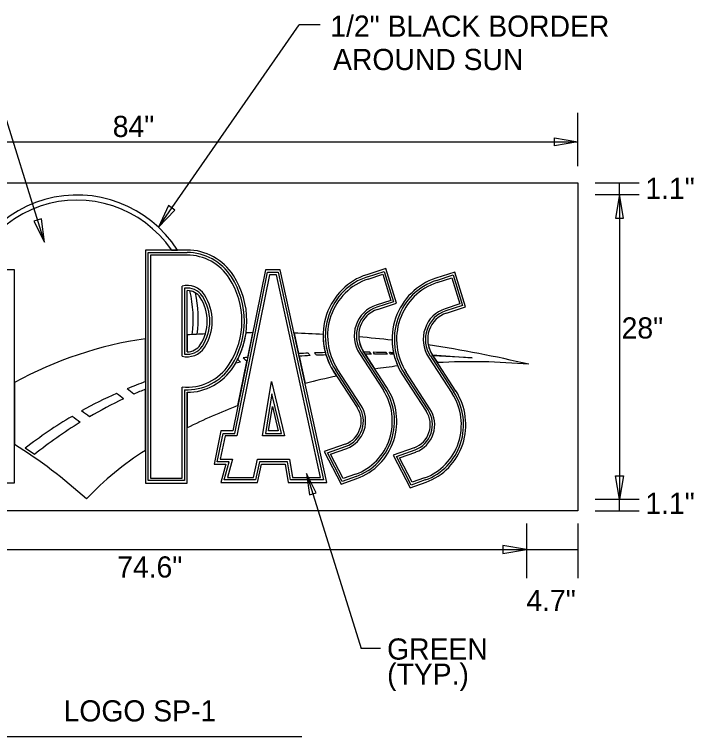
# Model space of a CAD drawing. Extents: x 10268197 to 10268738, y 2141503 to 2142677.
# Drawn here: x 10268635.31 to 10268657.77, y 2142399.46 to 2142423.33 of the extents above; entities that cross this region are included whole.
import ezdxf

# ---------------------------------------------------------------- set-up
doc = ezdxf.new("R2010")
doc.units = 0
for name, color, linetype in [('1', 7, 'Continuous'), ('Default', 7, 'Continuous'), ('GSDims', 7, 'Continuous')]:
    doc.layers.add(name, color=color, linetype=linetype)

msp = doc.modelspace()

# ---------------------------------------------------------------- linework, layer by layer
at = {"layer": '1'}
for p, q in [((10268640.072, 2142416.296), (10268644.725, 2142422.986)), ((10268645.427, 2142422.986), (10268644.725, 2142422.986)), ((10268636.311, 2142415.796), (10268634.409, 2142421.886)), ((10268642.605, 2142409.479), (10268643.683, 2142414.805)), ((10268643.683, 2142414.805), (10268644.037, 2142414.805)), ((10268644.037, 2142414.805), (10268645.537, 2142407.938)), ((10268642.88, 2142411.973), (10268642.994, 2142411.861)), ((10268643.827, 2142410.787), (10268643.614, 2142409.479)), ((10268644.146, 2142409.479), (10268643.827, 2142410.787)), ((10268644.039, 2142409.563), (10268643.713, 2142409.563)), ((10268642.018, 2142408.541), (10268642.212, 2142409.479)), ((10268642.212, 2142409.479), (10268642.605, 2142409.479)), ((10268643.614, 2142409.479), (10268644.146, 2142409.479)), ((10268641.916, 2142408.458), (10268642.308, 2142408.458)), ((10268642.417, 2142408.541), (10268642.018, 2142408.541)), ((10268642.254, 2142407.938), (10268642.417, 2142408.541)), ((10268643.416, 2142408.541), (10268643.286, 2142407.938)), ((10268644.339, 2142408.541), (10268643.416, 2142408.541)), ((10268644.437, 2142407.938), (10268644.339, 2142408.541)), ((10268644.974, 2142408.156), (10268646.782, 2142402.363)), ((10268643.286, 2142407.938), (10268642.254, 2142407.938)), ((10268645.537, 2142407.938), (10268644.437, 2142407.938)), ((10268647.421, 2142402.363), (10268646.782, 2142402.363))]:
    msp.add_line(p, q, dxfattribs=at)
for points in [[(10268642.308, 2142408.458), (10268642.144, 2142407.855), (10268643.353, 2142407.855), (10268643.484, 2142408.458), (10268644.268, 2142408.458), (10268644.366, 2142407.855), (10268645.641, 2142407.855), (10268644.105, 2142414.889), (10268643.615, 2142414.889), (10268642.536, 2142409.563), (10268642.144, 2142409.563), (10268641.916, 2142408.458)], [(10268642.672, 2142411.945), (10268642.791, 2142411.829), (10268642.63, 2142411.801)], [(10268643.713, 2142409.563), (10268643.843, 2142410.367), (10268644.039, 2142409.563)]]:
    msp.add_lwpolyline(points, dxfattribs=at)
at = {"layer": 'Default'}
for p, q in [((10268640.512, 2142415.539), (10268640.71, 2142415.539)), ((10268639.731, 2142407.919), (10268639.731, 2142415.455)), ((10268639.731, 2142415.455), (10268641.021, 2142415.455)), ((10268639.812, 2142415.372), (10268639.812, 2142408.002)), ((10268641.021, 2142415.372), (10268639.812, 2142415.372)), ((10268639.812, 2142415.372), (10268639.812, 2142408.002)), ((10268641.021, 2142415.372), (10268639.812, 2142415.372)), ((10268646.985, 2142414.652), (10268647.544, 2142414.833)), ((10268647.544, 2142414.833), (10268647.854, 2142413.827)), ((10268643.748, 2142414.722), (10268642.669, 2142409.396)), ((10268643.748, 2142414.722), (10268642.669, 2142409.396)), ((10268643.974, 2142414.722), (10268643.748, 2142414.722)), ((10268643.974, 2142414.722), (10268643.748, 2142414.722)), ((10268645.437, 2142408.022), (10268643.974, 2142414.722)), ((10268645.437, 2142408.022), (10268643.974, 2142414.722)), ((10268647.007, 2142414.58), (10268647.496, 2142414.738)), ((10268647.007, 2142414.58), (10268647.496, 2142414.738)), ((10268647.496, 2142414.738), (10268647.762, 2142413.876)), ((10268647.496, 2142414.738), (10268647.762, 2142413.876)), ((10268649.267, 2142414.533), (10268649.826, 2142414.714)), ((10268649.29, 2142414.461), (10268649.778, 2142414.619)), ((10268649.29, 2142414.461), (10268649.778, 2142414.619)), ((10268649.778, 2142414.619), (10268650.044, 2142413.757)), ((10268649.778, 2142414.619), (10268650.044, 2142413.757)), ((10268649.826, 2142414.714), (10268650.136, 2142413.708)), ((10268640.858, 2142412.028), (10268640.858, 2142414.347)), ((10268640.858, 2142412.028), (10268640.858, 2142414.347)), ((10268640.94, 2142414.277), (10268640.94, 2142412.098)), ((10268641.021, 2142412.176), (10268641.021, 2142414.199)), ((10268647.762, 2142413.876), (10268647.273, 2142413.718)), ((10268647.762, 2142413.876), (10268647.273, 2142413.718)), ((10268647.854, 2142413.827), (10268647.295, 2142413.646)), ((10268650.044, 2142413.757), (10268649.555, 2142413.599)), ((10268650.044, 2142413.757), (10268649.555, 2142413.599)), ((10268650.136, 2142413.708), (10268649.577, 2142413.527)), ((10268641.021, 2142412.734), (10268641.021, 2142412.176)), ((10268643.028, 2142411.991), (10268643.193, 2142412.807)), ((10268644.563, 2142412.79), (10268644.711, 2142412.114)), ((10268639.649, 2142411.189), (10268639.649, 2142412.605)), ((10268641.459, 2142412.407), (10268641.459, 2142412.407)), ((10268646.785, 2142412.159), (10268647.567, 2142410.956)), ((10268647.628, 2142410.998), (10268646.846, 2142412.201)), ((10268646.846, 2142412.201), (10268646.872, 2142412.16)), ((10268644.729, 2142412.028), (10268644.927, 2142411.123)), ((10268646.724, 2142412.117), (10268647.506, 2142410.914)), ((10268646.724, 2142412.117), (10268647.506, 2142410.914)), ((10268646.911, 2142412.101), (10268647.234, 2142411.605)), ((10268649.006, 2142411.999), (10268649.788, 2142410.795)), ((10268649.006, 2142411.999), (10268649.788, 2142410.795)), ((10268649.067, 2142412.04), (10268649.849, 2142410.837)), ((10268649.91, 2142410.879), (10268649.128, 2142412.082)), ((10268649.128, 2142412.082), (10268649.135, 2142412.072)), ((10268649.135, 2142412.072), (10268650.45, 2142411.975)), ((10268650.45, 2142411.975), (10268649.153, 2142412.044)), ((10268649.153, 2142412.044), (10268649.301, 2142411.816)), ((10268642.554, 2142411.676), (10268642.554, 2142411.676)), ((10268642.705, 2142410.398), (10268643.001, 2142411.859)), ((10268645.867, 2142411.532), (10268646.649, 2142410.329)), ((10268645.97, 2142411.374), (10268645.867, 2142411.532)), ((10268646.711, 2142410.371), (10268645.928, 2142411.574)), ((10268646.772, 2142410.413), (10268645.989, 2142411.616)), ((10268646.772, 2142410.413), (10268645.989, 2142411.616)), ((10268648.993, 2142410.252), (10268648.211, 2142411.455)), ((10268649.054, 2142410.294), (10268648.272, 2142411.497)), ((10268649.054, 2142410.294), (10268648.272, 2142411.497)), ((10268648.149, 2142411.413), (10268648.932, 2142410.21)), ((10268635.313, 2142411.156), (10268635.313, 2142409.116)), ((10268640.858, 2142408.002), (10268640.858, 2142411.011)), ((10268640.858, 2142408.002), (10268640.858, 2142411.011)), ((10268643.52, 2142409.396), (10268643.811, 2142411.189)), ((10268643.52, 2142409.396), (10268643.811, 2142411.189)), ((10268643.811, 2142411.189), (10268644.249, 2142409.396)), ((10268643.811, 2142411.189), (10268644.249, 2142409.396)), ((10268639.649, 2142408.916), (10268639.649, 2142410.939)), ((10268640.94, 2142410.922), (10268640.94, 2142407.919)), ((10268641.021, 2142410.836), (10268641.021, 2142409.661)), ((10268642.277, 2142409.396), (10268642.117, 2142408.625)), ((10268642.277, 2142409.396), (10268642.117, 2142408.625)), ((10268642.669, 2142409.396), (10268642.277, 2142409.396)), ((10268642.669, 2142409.396), (10268642.277, 2142409.396)), ((10268644.249, 2142409.396), (10268643.52, 2142409.396)), ((10268644.249, 2142409.396), (10268643.52, 2142409.396)), ((10268645.662, 2142408.833), (10268646.279, 2142409.054)), ((10268635.974, 2142408.781), (10268635.667, 2142408.987)), ((10268646.152, 2142407.891), (10268645.662, 2142408.833)), ((10268645.767, 2142408.791), (10268646.303, 2142408.982)), ((10268645.767, 2142408.791), (10268646.303, 2142408.982)), ((10268647.944, 2142408.714), (10268648.561, 2142408.935)), ((10268648.049, 2142408.672), (10268648.585, 2142408.863)), ((10268648.049, 2142408.672), (10268648.585, 2142408.863)), ((10268642.117, 2142408.625), (10268642.523, 2142408.625)), ((10268642.117, 2142408.625), (10268642.523, 2142408.625)), ((10268642.523, 2142408.625), (10268642.359, 2142408.022)), ((10268642.523, 2142408.625), (10268642.359, 2142408.022)), ((10268643.222, 2142408.022), (10268643.353, 2142408.625)), ((10268643.222, 2142408.022), (10268643.353, 2142408.625)), ((10268643.353, 2142408.625), (10268644.407, 2142408.625)), ((10268643.353, 2142408.625), (10268644.407, 2142408.625)), ((10268644.407, 2142408.625), (10268644.505, 2142408.022)), ((10268644.407, 2142408.625), (10268644.505, 2142408.022)), ((10268646.187, 2142407.983), (10268645.767, 2142408.791)), ((10268646.187, 2142407.983), (10268645.767, 2142408.791)), ((10268648.434, 2142407.772), (10268647.944, 2142408.714)), ((10268648.47, 2142407.864), (10268648.049, 2142408.672)), ((10268648.47, 2142407.864), (10268648.049, 2142408.672)), ((10268646.593, 2142408.128), (10268646.187, 2142407.983)), ((10268646.593, 2142408.128), (10268646.187, 2142407.983)), ((10268640.94, 2142407.919), (10268639.731, 2142407.919)), ((10268639.812, 2142408.002), (10268640.858, 2142408.002)), ((10268639.812, 2142408.002), (10268640.858, 2142408.002)), ((10268642.359, 2142408.022), (10268643.222, 2142408.022)), ((10268642.359, 2142408.022), (10268643.222, 2142408.022)), ((10268644.505, 2142408.022), (10268645.437, 2142408.022)), ((10268644.505, 2142408.022), (10268645.437, 2142408.022)), ((10268646.617, 2142408.057), (10268646.152, 2142407.891)), ((10268648.899, 2142407.938), (10268648.434, 2142407.772)), ((10268648.875, 2142408.009), (10268648.47, 2142407.864)), ((10268648.875, 2142408.009), (10268648.47, 2142407.864)), ((10268653.948, 2142406.917), (10268624.544, 2142406.917)), ((10268634.39, 2142399.458), (10268644.821, 2142399.458))]:
    msp.add_line(p, q, dxfattribs=at)
for points in [[(10268624.544, 2142406.917), (10268624.544, 2142417.76), (10268653.948, 2142417.76), (10268653.948, 2142406.917)], [(10268641.021, 2142415.539), (10268639.649, 2142415.539), (10268639.649, 2142407.835), (10268641.021, 2142407.835), (10268641.021, 2142410.836)], [(10268632.143, 2142407.978), (10268633.352, 2142407.978), (10268633.352, 2142410.859), (10268634.888, 2142407.844), (10268635.313, 2142407.844), (10268635.313, 2142414.879), (10268634.071, 2142414.879), (10268634.071, 2142412.065), (10268632.633, 2142415.013), (10268632.143, 2142415.013)], [(10268647.317, 2142413.574), (10268647.946, 2142413.777), (10268647.592, 2142414.927), (10268646.963, 2142414.724)], [(10268649.599, 2142413.455), (10268650.228, 2142413.658), (10268649.874, 2142414.808), (10268649.245, 2142414.605)], [(10268642.486, 2142414.653), (10268642.486, 2142414.653)], [(10268641.527, 2142414.014), (10268641.526, 2142414.016)], [(10268641.459, 2142412.407), (10268641.459, 2142412.407)], [(10268641.526, 2142412.359), (10268641.527, 2142412.36)], [(10268642.696, 2142411.922), (10268642.791, 2142411.829), (10268642.63, 2142411.801)], [(10268642.486, 2142411.722), (10268642.486, 2142411.722)], [(10268642.554, 2142411.676), (10268642.554, 2142411.676)], [(10268643.001, 2142411.859), (10268642.994, 2142411.861)], [(10268646.255, 2142409.125), (10268645.556, 2142408.876), (10268646.117, 2142407.799), (10268646.641, 2142407.986)], [(10268648.537, 2142409.006), (10268647.839, 2142408.757), (10268648.399, 2142407.68), (10268648.924, 2142407.867)]]:
    msp.add_lwpolyline(points, dxfattribs=at)
for centre, major_axis, ratio, start_param, end_param in [((10268637.386, 2142413.254), (0, 4.102), 0.97582, 5.303349, 7.802858), ((10268637.386, 2142413.254), (0, 4.102), 0.97582, 5.303349, 7.802858), ((10268637.386, 2142413.254), (0, 3.935), 0.97582, 5.332201, 7.884008), ((10268637.386, 2142413.254), (0, 3.935), 0.97582, 5.332201, 7.884008), ((10268641.025, 2142413.658), (0, 1.881), 0.97582, 5.298823, 6.285263), ((10268641.025, 2142413.658), (0, 1.798), 0.97582, 5.29886, 6.285263), ((10268641.021, 2142413.689), (0, 1.682), 0.990269, 5.289759, 6.283185), ((10268641.021, 2142413.689), (0, 1.682), 0.990269, 5.289759, 6.283185), ((10268640.259, 2142413.187), (0, 2.602), 0.989796, 4.135019, 5.289759), ((10268640.259, 2142413.187), (0, 2.602), 0.989796, 4.135019, 5.289759), ((10268641.025, 2142413.658), (0, 1.798), 0.97582, 5.298823, 5.29886), ((10268640.326, 2142413.187), (0, 2.655), 0.97582, 4.127723, 5.297054), ((10268640.326, 2142413.187), (0, 2.655), 0.97582, 5.297054, 5.297084), ((10268640.326, 2142413.187), (0, 2.739), 0.97582, 4.127694, 5.297084), ((10268647.586, 2142412.706), (0, 2.116), 0.97582, 0.306207, 2.15869), ((10268647.586, 2142412.706), (0, 2.041), 0.97582, 0.306207, 2.15869), ((10268647.585, 2142412.706), (0, 1.965), 0.975477, 0.305879, 2.158799), ((10268647.585, 2142412.706), (0, 1.965), 0.975477, 0.305879, 2.158799), ((10268649.868, 2142412.587), (0, 2.116), 0.97582, 0.306207, 2.15869), ((10268649.868, 2142412.587), (0, 2.041), 0.97582, 0.306207, 2.15869), ((10268641.021, 2142413.689), (0.686, 0), 0.987937, 0.57737, 1.811353), ((10268641.021, 2142413.689), (0.686, 0), 0.987937, 0.57737, 1.811353), ((10268641.026, 2142413.658), (0, 0.625), 0.97582, 5.321397, 6.424928), ((10268649.867, 2142412.587), (0, 1.965), 0.975477, 0.305879, 2.158799), ((10268649.867, 2142412.587), (0, 1.965), 0.975477, 0.305879, 2.158799), ((10268641.026, 2142413.658), (0, 0.541), 0.97582, 5.321397, 6.29161), ((10268637.386, 2142413.254), (0, 3.935), 0.97582, 4.58247, 4.952925), ((10268641.021, 2142413.689), (0.522, 0), 0.976302, 1.01124, 1.389925), ((10268637.386, 2142413.254), (0, 3.935), 0.97582, 4.58247, 4.952925), ((10268637.386, 2142413.254), (0, 4.102), 0.97582, 4.590045, 4.925551), ((10268637.386, 2142413.254), (0, 4.102), 0.97582, 4.590045, 4.925551), ((10268640.259, 2142413.187), (0, 1.597), 0.998806, 4.135019, 5.289759), ((10268640.259, 2142413.187), (0, 1.597), 0.998806, 4.135019, 5.289759), ((10268640.326, 2142413.187), (0, 1.399), 0.97582, 4.120664, 5.304114), ((10268640.326, 2142413.187), (0, 1.483), 0.97582, 4.120664, 5.304114), ((10268647.585, 2142412.706), (0, 1.061), 0.975477, 0.305879, 2.158799), ((10268647.585, 2142412.706), (0, 1.061), 0.975477, 0.305879, 2.158799), ((10268647.585, 2142412.706), (0, 0.986), 0.97582, 0.306207, 2.15869), ((10268649.867, 2142412.587), (0, 1.061), 0.975477, 0.305879, 2.158799), ((10268649.867, 2142412.587), (0, 1.061), 0.975477, 0.305879, 2.158799), ((10268647.585, 2142412.706), (0, 0.91), 0.97582, 0.306207, 2.15869), ((10268649.867, 2142412.587), (0, 0.986), 0.97582, 0.306207, 2.15869), ((10268649.867, 2142412.587), (0, 0.91), 0.97582, 0.306207, 2.15869), ((10268643.408, 2142373.443), (0, -39.365), 0.98893, 3.187344, 3.202947), ((10268643.408, 2142373.443), (0, -39.365), 0.98893, 3.187344, 3.202947), ((10268643.408, 2142373.443), (0, -39.365), 0.98893, 3.194251, 3.198517), ((10268640.326, 2142413.187), (0, 1.399), 0.97582, 4.120664, 4.406744), ((10268640.326, 2142413.187), (0, 2.739), 0.97582, 4.232077, 4.572378), ((10268643.408, 2142373.443), (0, -39.365), 0.98893, 3.147118, 3.152801), ((10268643.408, 2142373.443), (0, -39.365), 0.98893, 3.147118, 3.152801), ((10268643.408, 2142373.443), (0, -39.365), 0.98893, 3.087298, 3.111926), ((10268643.408, 2142373.443), (0, -39.365), 0.98893, 3.087298, 3.111926), ((10268647.586, 2142412.706), (0, 2.116), 0.97582, 1.5501, 1.838244), ((10268643.408, 2142373.443), (0, -39.365), 0.98893, 3.028464, 3.056997), ((10268643.408, 2142373.443), (0, -39.365), 0.98893, 3.028464, 3.056997), ((10268647.585, 2142412.706), (0, 0.91), 0.97582, 1.61365, 2.15869), ((10268641.439, 2142399.446), (0, 13.287), 0.97582, 0.138501, 0.492135), ((10268641.439, 2142399.446), (0, 13.287), 0.97582, 0.138501, 0.492135), ((10268641.025, 2142412.718), (0, 0.543), 0.97582, 3.134436, 4.102113), ((10268641.025, 2142412.718), (0, 0.543), 0.97582, 3.134436, 4.102113), ((10268649.868, 2142412.587), (0, 2.116), 0.97582, 1.58538, 1.781939), ((10268643.408, 2142373.443), (0, -39.365), 0.98893, 2.910551, 2.997508), ((10268643.408, 2142373.443), (0, -39.365), 0.98893, 2.910551, 2.997508), ((10268649.867, 2142412.587), (0, 0.91), 0.97582, 1.777902, 2.15869), ((10268641.021, 2142412.686), (0.686, 0), 0.987937, 4.471833, 5.705815), ((10268641.021, 2142412.686), (0.686, 0), 0.987937, 4.471833, 5.705815), ((10268641.025, 2142412.718), (0, 0.626), 0.97582, 3.001239, 4.102113), ((10268646.663, 2142370.723), (0, -41.438), 0.988257, 3.167715, 3.176345), ((10268646.663, 2142370.723), (0, -41.438), 0.988257, 3.131695, 3.136489), ((10268626.606, 2142394.871), (0, 27.046), 0.983807, 5.403078, 5.405838), ((10268646.663, 2142370.723), (0, -41.438), 0.988257, 3.118574, 3.129071), ((10268626.606, 2142394.871), (0, 27.129), 0.983781, 5.400528, 5.403217), ((10268626.606, 2142394.871), (0, 27.464), 0.98368, 5.390405, 5.392813), ((10268626.606, 2142394.871), (0, 27.548), 0.983655, 5.387892, 5.390232), ((10268646.663, 2142370.723), (0, -41.438), 0.988257, 3.112651, 3.11595), ((10268644.708, 2142397.005), (0, -15.082), 0.987081, 3.2547, 3.264672), ((10268626.606, 2142394.871), (0, 23.78), 0.984951, 5.508238, 5.514999), ((10268646.663, 2142370.723), (0, -41.438), 0.988257, 3.181604, 3.189295), ((10268647.157, 2142370.663), (0, -41.438), 0.988257, 3.191919, 3.200901), ((10268626.606, 2142394.871), (0, 25.455), 0.984327, 5.453123, 5.457325), ((10268626.606, 2142394.871), (0, 25.622), 0.98427, 5.447702, 5.451744), ((10268647.157, 2142370.663), (0, -41.438), 0.988257, 3.179241, 3.186723), ((10268647.586, 2142412.706), (0, 2.116), 0.97582, 1.875041, 2.15869), ((10268647.157, 2142370.663), (0, -41.438), 0.988257, 3.142595, 3.147585), ((10268647.157, 2142370.663), (0, -41.438), 0.988257, 3.129621, 3.14), ((10268647.157, 2142370.663), (0, -41.438), 0.988257, 3.124437, 3.127026), ((10268649.868, 2142412.587), (0, 2.116), 0.97582, 1.805305, 2.000126), ((10268641.021, 2142412.686), (0, 1.682), 0.990269, 3.043371, 4.135019), ((10268641.021, 2142412.686), (0, 1.682), 0.990269, 3.043371, 4.135019), ((10268641.025, 2142412.717), (0, 1.798), 0.97582, 3.092812, 4.125918), ((10268641.025, 2142412.717), (0, 1.881), 0.97582, 3.139515, 4.125955), ((10268641.025, 2142412.717), (0, 1.881), 0.97582, 3.139515, 4.125955), ((10268641.025, 2142412.717), (0, 1.798), 0.97582, 4.125918, 4.125955), ((10268640.326, 2142413.187), (0, 2.655), 0.97582, 4.127694, 4.127723), ((10268640.326, 2142413.187), (0, 2.739), 0.97582, 4.127694, 4.181576), ((10268650.429, 2142389.475), (0, 22.371), 0.975477, 0.111981, 0.146944), ((10268650.429, 2142389.475), (0, 22.371), 0.975477, 0.111981, 0.146944), ((10268650.429, 2142389.475), (0, 22.371), 0.975477, 6.196281, 6.334881), ((10268650.429, 2142389.475), (0, 22.371), 0.975477, 6.196281, 6.334881), ((10268650.429, 2142389.475), (0, 22.371), 0.975477, 0.20577, 0.254866), ((10268650.429, 2142389.475), (0, 22.371), 0.975477, 0.20577, 0.254866), ((10268644.708, 2142397.005), (0, -15.082), 0.987081, 3.48834, 3.532255), ((10268645.996, 2142409.884), (0, 1.934), 0.97582, 3.476656, 5.300276), ((10268645.996, 2142409.884), (0, 2.01), 0.97582, 3.476656, 5.300276), ((10268644.708, 2142397.005), (0, -15.082), 0.987081, 3.557551, 3.644446), ((10268626.606, 2142394.871), (0, 20.095), 0.986688, 5.613012, 5.627647), ((10268626.606, 2142394.871), (0, 20.43), 0.986504, 5.604488, 5.618403), ((10268645.201, 2142396.946), (0, -15.082), 0.987081, 3.5238, 3.552221), ((10268645.997, 2142409.884), (0, -1.859), 0.975477, 0.334737, 2.158799), ((10268645.997, 2142409.884), (0, -1.859), 0.975477, 0.334737, 2.158799), ((10268648.28, 2142409.765), (0, -1.859), 0.975477, 0.334737, 2.158799), ((10268648.28, 2142409.765), (0, -1.859), 0.975477, 0.334737, 2.158799), ((10268648.279, 2142409.765), (0, 1.934), 0.97582, 3.476656, 5.300276), ((10268648.279, 2142409.765), (0, 2.01), 0.97582, 3.476656, 5.300276), ((10268645.201, 2142396.946), (0, -15.082), 0.987081, 3.577057, 3.66248), ((10268650.429, 2142389.475), (0, 22.371), 0.975477, 0.36175, 0.445699), ((10268650.429, 2142389.475), (0, 22.371), 0.975477, 0.36175, 0.445699), ((10268645.997, 2142409.884), (0, 0.804), 0.97582, 3.476661, 5.300276), ((10268645.997, 2142409.884), (0, 0.879), 0.97582, 3.476661, 5.300276), ((10268645.997, 2142409.884), (0, -0.954), 0.975477, 0.334742, 2.158799), ((10268645.997, 2142409.884), (0, -0.954), 0.975477, 0.334742, 2.158799), ((10268648.279, 2142409.765), (0, 0.879), 0.97582, 3.476661, 5.300276), ((10268648.28, 2142409.765), (0, -0.954), 0.975477, 0.334742, 2.158799), ((10268648.28, 2142409.765), (0, -0.954), 0.975477, 0.334742, 2.158799), ((10268644.708, 2142397.005), (0, -15.082), 0.987081, 3.668845, 3.794286), ((10268626.606, 2142394.871), (0, 18.588), 0.987597, 5.648885, 5.666846), ((10268626.606, 2142394.871), (0, 18.923), 0.987382, 5.641271, 5.658477), ((10268648.279, 2142409.765), (0, 0.804), 0.97582, 3.476661, 5.300276), ((10268645.201, 2142396.946), (0, -15.082), 0.987081, 3.686493, 3.810103), ((10268626.675, 2142394.606), (0, 16.997), 0.97582, 5.556667, 5.735414), ((10268626.675, 2142394.606), (0, 16.997), 0.97582, 5.556667, 5.735414), ((10268644.824, 2142400.447), (0, -9.956), 0.98893, 3.695067, 3.951695), ((10268644.824, 2142400.447), (0, -9.956), 0.98893, 3.695067, 3.951695)]:
    msp.add_ellipse(centre, major_axis=major_axis, ratio=ratio, start_param=start_param, end_param=end_param, dxfattribs=at)
at = {"layer": 'GSDims'}
for p, q in [((10268653.948, 2142418.305), (10268653.948, 2142420.074)), ((10268624.544, 2142419.113), (10268653.948, 2142419.113)), ((10268654.518, 2142417.76), (10268655.975, 2142417.76)), ((10268655.322, 2142417.37), (10268655.322, 2142417.76)), ((10268654.518, 2142417.37), (10268655.975, 2142417.37)), ((10268655.322, 2142417.37), (10268655.322, 2142407.302)), ((10268654.518, 2142407.302), (10268655.975, 2142407.302)), ((10268655.322, 2142406.917), (10268655.322, 2142407.302)), ((10268654.518, 2142406.917), (10268655.975, 2142406.917)), ((10268652.243, 2142406.497), (10268652.243, 2142404.694)), ((10268653.948, 2142406.497), (10268653.948, 2142404.694)), ((10268626.195, 2142405.64), (10268652.243, 2142405.64)), ((10268652.243, 2142405.64), (10268653.948, 2142405.64))]:
    msp.add_line(p, q, dxfattribs=at)
for points in [[(10268653.948, 2142419.113), (10268653.174, 2142418.983), (10268653.174, 2142419.242)], [(10268655.322, 2142417.37), (10268655.193, 2142416.596), (10268655.452, 2142416.596)], [(10268640.072, 2142416.296), (10268640.62, 2142416.858), (10268640.408, 2142417.005)], [(10268636.311, 2142415.796), (10268636.203, 2142416.574), (10268635.957, 2142416.497)], [(10268644.974, 2142408.156), (10268645.071, 2142407.449), (10268645.295, 2142407.519)], [(10268655.322, 2142407.302), (10268655.193, 2142408.076), (10268655.452, 2142408.076)], [(10268652.243, 2142405.64), (10268651.469, 2142405.769), (10268651.469, 2142405.511)]]:
    msp.add_lwpolyline(points, close=True, dxfattribs=at)

# ---------------------------------------------------------------- texts
at = {"layer": '1'}
for s, p in [('1/2" BLACK BORDER', (10268645.759, 2142422.588)), ('AROUND SUN', (10268645.851, 2142421.487)), ('84"', (10268638.564, 2142419.275)), ('1.1"', (10268656.179, 2142417.227)), ('28"', (10268655.394, 2142412.614)), ('1.1"', (10268656.179, 2142406.818)), ('74.6"', (10268638.711, 2142404.714)), ('4.7"', (10268652.244, 2142403.607)), ('GREEN', (10268647.638, 2142402.001)), ('(TYP.)', (10268647.638, 2142401.17)), ('LOGO SP-1', (10268636.939, 2142399.957))]:
    msp.add_text(s, height=0.7, dxfattribs=at).set_placement(p)

doc.saveas('drawing.dxf')
